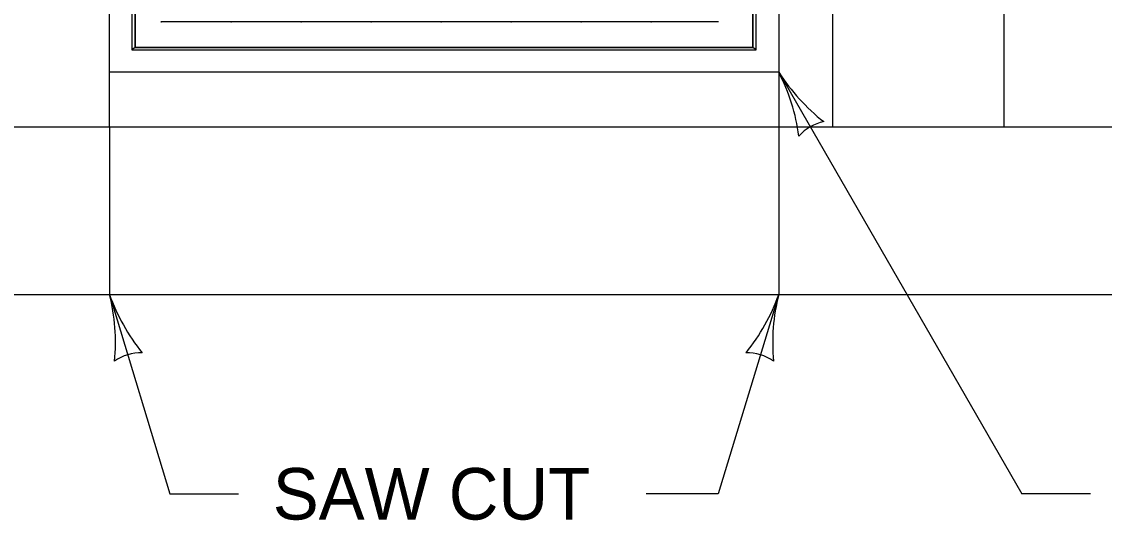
# Model space of a CAD drawing. Extents: x 49991.4 to 50021, y 49987.6 to 50011.4.
# Drawn here: x 50009.515 to 50010.777, y 49993.244 to 49993.825 of the extents above; entities that cross this region are included whole.
import ezdxf

# ---------------------------------------------------------------- set-up
doc = ezdxf.new("R2010")
doc.units = 0
for name, color, linetype in [('Level 1', 7, 'Continuous'), ('Level 18', 7, 'Continuous'), ('Level 2', 7, 'Continuous'), ('Level 3', 7, 'Continuous'), ('Level 4', 7, 'Continuous')]:
    doc.layers.add(name, color=color, linetype=linetype)

msp = doc.modelspace()

# ---------------------------------------------------------------- linework, layer by layer
at = {"layer": 'Level 1'}
for p, q in [((50009.6173, 49993.702), (50009.6173, 49994.4256)), ((50010.3973, 49994.4256), (50010.3973, 49993.702)), ((50009.6436, 49994.3993), (50009.6436, 49993.792)), ((50010.3673, 49993.7946), (50010.3673, 49994.3945)), ((50010.3711, 49993.792), (50010.3711, 49994.3993)), ((50010.3273, 49993.8246), (50009.6773, 49993.8246)), ((50009.6473, 49993.7946), (50009.6436, 49993.792)), ((50009.6436, 49993.792), (50010.3711, 49993.792)), ((50009.6473, 49993.7946), (50010.3673, 49993.7946)), ((50010.2281, 49993.792), (50010.3636, 49993.792)), ((50010.3711, 49993.792), (50010.3673, 49993.7946)), ((50010.3973, 49993.7657), (50009.6173, 49993.7657)), ((50008.9753, 49993.702), (50009.6173, 49993.702)), ((50009.6173, 49993.702), (50010.3973, 49993.702)), ((50009.6173, 49993.702), (50009.6173, 49993.507)), ((50010.3973, 49993.702), (50012.0913, 49993.702)), ((50010.3973, 49993.702), (50010.3973, 49993.507)), ((50008.9753, 49993.507), (50012.0913, 49993.507))]:
    msp.add_line(p, q, dxfattribs=at)
msp.add_lwpolyline([(50009.6473, 49994.3945), (50010.3672, 49994.3945), (50010.3672, 49993.7946), (50009.6473, 49993.7946)], close=True, dxfattribs=at)
for centre, start_param, end_param in [((50009.7589, 49993.8249), 3.141593, 4.712389), ((50009.7589, 49993.8249), 4.712389, 5.141186), ((50009.8404, 49993.8249), 3.141593, 4.712389), ((50009.8404, 49993.8249), 4.712389, 5.141186), ((50009.922, 49993.8249), 3.141593, 4.712389), ((50009.922, 49993.8249), 4.712389, 5.141186), ((50010.0035, 49993.8249), 3.141593, 4.712389), ((50010.0035, 49993.8249), 4.712389, 5.141186), ((50010.085, 49993.8249), 3.141593, 4.712389), ((50010.085, 49993.8249), 4.712389, 5.141186), ((50010.1666, 49993.8249), 3.141593, 4.712389), ((50010.1666, 49993.8249), 4.712389, 5.141186), ((50010.2481, 49993.8249), 3.141593, 4.712389)]:
    msp.add_ellipse(centre, major_axis=(0.00375, 0), ratio=0.076923, start_param=start_param, end_param=end_param, dxfattribs=at)
at = {"layer": 'Level 18'}
msp.add_line((50009.6473, 49994.3945), (50009.6473, 49993.7946), dxfattribs=at)
for centre in [(50009.6773, 49993.8249), (50010.2481, 49993.8249)]:
    msp.add_ellipse(centre, major_axis=(0.00375, 0), ratio=0.076923, start_param=4.712389, end_param=5.141186, dxfattribs=at)
at = {"layer": 'Level 2'}
for p, q in [((50010.3973, 49993.7657), (50010.6808, 49993.2748)), ((50009.6173, 49993.507), (50009.6877, 49993.2748)), ((50010.3973, 49993.507), (50010.3269, 49993.2748)), ((50009.6877, 49993.2748), (50009.7677, 49993.2748)), ((50010.3269, 49993.2748), (50010.2428, 49993.2748)), ((50010.7608, 49993.2748), (50010.6808, 49993.2748))]:
    msp.add_line(p, q, dxfattribs=at)
at = {"layer": 'Level 3'}
for centre, radius, start, end in [((50010.2004, 49993.6626), 0.2223, 7.456, 27.6395), ((50010.5931, 49993.892), 0.233, 212.8273, 232.0772), ((50010.4614, 49993.6547), 0.0548, 102.1388, 137.8612), ((50009.4021, 49993.4513), 0.2223, 354.3201, 14.5036), ((50009.8367, 49993.5855), 0.233, 199.6914, 218.9413), ((50010.178, 49993.5855), 0.233, 321.0587, 340.3086), ((50010.6126, 49993.4513), 0.2223, 165.4964, 185.6799), ((50009.6545, 49993.3843), 0.0548, 89.0029, 124.7253), ((50010.3601, 49993.3843), 0.0548, 55.2747, 90.9971)]:
    msp.add_arc(centre, radius, start, end, dxfattribs=at)
at = {"layer": 'Level 4'}
for p, q in [((50010.4598, 49994.902), (50010.4598, 49993.702)), ((50010.6598, 49994.902), (50010.6598, 49993.702))]:
    msp.add_line(p, q, dxfattribs=at)

# ---------------------------------------------------------------- texts
at = {"layer": 'Level 2'}
msp.add_text('SAW CUT', height=0.06, dxfattribs=at).set_placement((50009.8077, 49993.2448))

doc.saveas('drawing.dxf')
